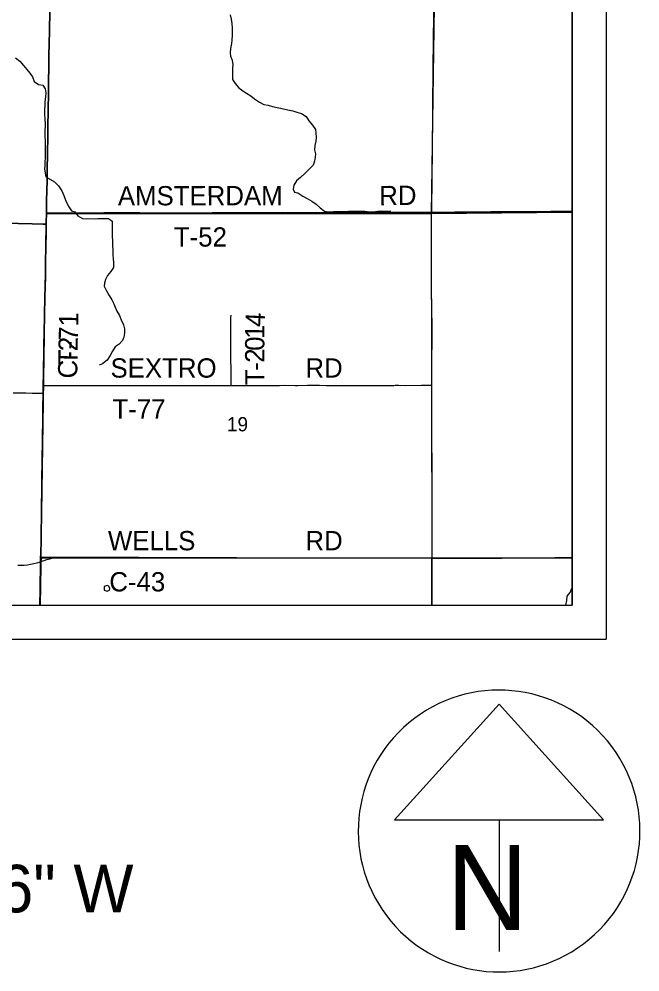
# Model space of a CAD drawing. Extents: x -11.1 to 34, y -3.9 to 22.
# Drawn here: x 7.271 to 9.099, y 13.02 to 15.825 of the extents above; entities that cross this region are included whole.
import ezdxf

# ---------------------------------------------------------------- set-up
doc = ezdxf.new("R2010")
doc.units = 0
for name, color, linetype in [('GM_X_Corporation', 7, 'Continuous'), ('GM_X_County_Road', 7, 'Continuous'), ('GM_X_County_Road_Text', 7, 'Continuous'), ('GM_X_Minor_Lake', 7, 'Continuous'), ('GM_X_Minor_River', 7, 'Continuous'), ('GM_X_Section_Text', 7, 'Continuous'), ('GM_X_Township_Road', 7, 'Continuous'), ('GM_X_Township_Road_Text', 7, 'Continuous'), ('SH_Data', 7, 'Continuous'), ('SH_Text', 7, 'Continuous')]:
    doc.layers.add(name, color=color, linetype=linetype)

msp = doc.modelspace()

# ---------------------------------------------------------------- linework, layer by layer
at = {"layer": 'GM_X_Corporation'}
for points in [[(7.3613, 15.8526), (7.3601, 15.7867), (7.3596, 15.7569), (7.3589, 15.7153), (7.3582, 15.6817), (7.3577, 15.6439), (7.3576, 15.6308), (7.3573, 15.6078), (7.356, 15.5071), (7.3554, 15.4686), (7.3548, 15.4413), (7.3545, 15.4251), (7.3538, 15.3866), (7.3533, 15.3537), (7.3525, 15.3176), (7.3519, 15.2928), (7.3513, 15.2636), (7.3512, 15.2541), (7.3508, 15.2263), (7.3508, 15.2219), (7.3507, 15.1996), (7.3497, 15.1505), (7.349, 15.1132), (7.3483, 15.0666), (7.3471, 15.0082), (7.3458, 14.9523), (7.345, 14.9013), (7.3443, 14.8653), (7.3436, 14.8274), (7.3433, 14.8131), (7.3425, 14.7765), (7.3422, 14.7516), (7.3421, 14.7474), (7.3418, 14.7293), (7.3418, 14.7242), (7.3413, 14.6802), (7.3406, 14.6373), (7.34, 14.6025), (7.3394, 14.5733), (7.3389, 14.5404), (7.3387, 14.5118), (7.3383, 14.482), (7.3381, 14.4702), (7.3376, 14.4223), (7.3373, 14.408), (7.3366, 14.3484), (7.3363, 14.3291), (7.3361, 14.3123), (7.3355, 14.2893), (7.3346, 14.2521), (7.3343, 14.2397), (7.3341, 14.2279), (7.3337, 14.1993), (7.3332, 14.1738), (7.3327, 14.1458), (7.332, 14.1), (8.9, 14.1), (8.9, 19.2515)], [(7.3613, 15.8526), (7.3601, 15.7867), (7.3596, 15.7569), (7.3589, 15.7153), (7.3582, 15.6817), (7.3577, 15.6439), (7.3576, 15.6308), (7.3573, 15.6078), (7.356, 15.5071), (7.3554, 15.4686), (7.3548, 15.4413), (7.3545, 15.4251), (7.3538, 15.3866), (7.3533, 15.3537), (7.3525, 15.3176), (7.3519, 15.2928), (7.3513, 15.2636), (7.3512, 15.2541), (7.3522, 15.2541), (7.3626, 15.2543), (7.3874, 15.2543), (7.4377, 15.2541), (7.4824, 15.2544), (7.5203, 15.2546), (7.5502, 15.2545), (7.6017, 15.2545), (7.6266, 15.2545), (7.6856, 15.2543), (7.7416, 15.2543), (7.8398, 15.2545), (7.887, 15.2546), (7.9286, 15.2547), (7.979, 15.255), (8.0479, 15.2555), (8.1126, 15.2553), (8.1704, 15.2555), (8.2008, 15.2555), (8.2294, 15.2555), (8.2341, 15.2556), (8.2679, 15.2556), (8.3083, 15.2559), (8.3512, 15.2561), (8.3785, 15.2559), (8.4202, 15.2558), (8.4699, 15.2559), (8.4858, 15.256), (8.5022, 15.2559), (8.5538, 15.2566), (8.6115, 15.257), (8.66, 15.2575), (8.6849, 15.2577), (8.7085, 15.258), (8.7377, 15.2577), (8.7843, 15.2582), (8.8365, 15.2585), (8.8595, 15.2587), (8.9, 15.2587), (8.9, 19.2515)], [(2.1, 14.1), (7.332, 14.1), (7.3327, 14.1458), (7.3332, 14.1738), (7.3337, 14.1993), (7.3341, 14.2279), (7.3343, 14.2397), (7.3346, 14.2521), (7.3355, 14.2893), (7.3361, 14.3123), (7.3363, 14.3291), (7.3366, 14.3484), (7.3373, 14.408), (7.3376, 14.4223), (7.3381, 14.4702), (7.3383, 14.482), (7.3387, 14.5118), (7.3389, 14.5404), (7.3394, 14.5733), (7.34, 14.6025), (7.3406, 14.6373), (7.3413, 14.6802), (7.3418, 14.7242), (7.3418, 14.7293), (7.3421, 14.7474), (7.3422, 14.7516), (7.3425, 14.7765), (7.3433, 14.8131), (7.3436, 14.8274), (7.3443, 14.8653), (7.345, 14.9013), (7.3458, 14.9523), (7.3471, 15.0082), (7.3483, 15.0666), (7.349, 15.1132), (7.3497, 15.1505), (7.3507, 15.1996), (7.3508, 15.2219), (7.3508, 15.2263), (7.3512, 15.2541), (7.3513, 15.2636), (7.3519, 15.2928), (7.3525, 15.3176), (7.3533, 15.3537), (7.3538, 15.3866), (7.3545, 15.4251), (7.3548, 15.4413), (7.3554, 15.4686), (7.356, 15.5071), (7.3573, 15.6078), (7.3576, 15.6308), (7.3577, 15.6439), (7.3582, 15.6817), (7.3589, 15.7153), (7.3596, 15.7569), (7.3601, 15.7867), (7.3613, 15.8526)], [(6.3599, 15.2448), (7.3508, 15.2219), (7.3508, 15.2263), (7.3512, 15.2541), (7.3513, 15.2636), (7.3519, 15.2928), (7.3525, 15.3176), (7.3533, 15.3537), (7.3538, 15.3866), (7.3545, 15.4251), (7.3548, 15.4413), (7.3554, 15.4686), (7.356, 15.5071), (7.3573, 15.6078), (7.3576, 15.6308), (7.3577, 15.6439), (7.3582, 15.6817), (7.3589, 15.7153), (7.3596, 15.7569), (7.3601, 15.7867), (7.3613, 15.8526)], [(2.1, 14.1), (7.332, 14.1), (7.3327, 14.1458), (7.3332, 14.1738), (7.3337, 14.1993), (7.3341, 14.2279), (7.3343, 14.2397), (7.3346, 14.2521), (7.3355, 14.2893), (7.3361, 14.3123), (7.3363, 14.3291), (7.3366, 14.3484), (7.3373, 14.408), (7.3376, 14.4223), (7.3381, 14.4702), (7.3383, 14.482), (7.3387, 14.5118), (7.3389, 14.5404), (7.3394, 14.5733), (7.34, 14.6025), (7.3406, 14.6373), (7.3413, 14.6802), (7.3418, 14.7242), (7.3418, 14.7293), (7.3421, 14.7474), (7.3422, 14.7516), (7.3425, 14.7765), (7.3433, 14.8131), (7.3436, 14.8274), (7.3443, 14.8653), (7.345, 14.9013), (7.3458, 14.9523), (7.3471, 15.0082), (7.3483, 15.0666), (7.349, 15.1132), (7.3497, 15.1505), (7.3507, 15.1996), (7.3508, 15.2219), (6.3599, 15.2448)]]:
    msp.add_lwpolyline(points, dxfattribs=at)
for points in [[(8.9, 15.2568), (8.9, 16.2758), (8.4993, 16.2731), (8.4849, 15.2528)], [(7.332, 14.1), (8.9, 14.1), (8.9, 15.2587), (8.8595, 15.2587), (8.8365, 15.2585), (8.7843, 15.2582), (8.7377, 15.2577), (8.7085, 15.258), (8.6849, 15.2577), (8.66, 15.2575), (8.6115, 15.257), (8.5538, 15.2566), (8.5022, 15.2559), (8.4858, 15.256), (8.4699, 15.2559), (8.4202, 15.2558), (8.3785, 15.2559), (8.3512, 15.2561), (8.3083, 15.2559), (8.2679, 15.2556), (8.2341, 15.2556), (8.2294, 15.2555), (8.2008, 15.2555), (8.1704, 15.2555), (8.1126, 15.2553), (8.0479, 15.2555), (7.979, 15.255), (7.9286, 15.2547), (7.887, 15.2546), (7.8398, 15.2545), (7.7416, 15.2543), (7.6856, 15.2543), (7.6266, 15.2545), (7.6017, 15.2545), (7.5502, 15.2545), (7.5203, 15.2546), (7.4824, 15.2544), (7.4377, 15.2541), (7.3874, 15.2543), (7.3626, 15.2543), (7.3522, 15.2541), (7.3512, 15.2541), (7.3508, 15.2263), (7.3508, 15.2219), (7.3507, 15.1996), (7.3497, 15.1505), (7.349, 15.1132), (7.3483, 15.0666), (7.3471, 15.0082), (7.3458, 14.9523), (7.345, 14.9013), (7.3443, 14.8653), (7.3436, 14.8274), (7.3433, 14.8131), (7.3425, 14.7765), (7.3422, 14.7516), (7.3421, 14.7474), (7.3418, 14.7293), (7.3418, 14.7242), (7.3413, 14.6802), (7.3406, 14.6373), (7.34, 14.6025), (7.3394, 14.5733), (7.3389, 14.5404), (7.3387, 14.5118), (7.3383, 14.482), (7.3381, 14.4702), (7.3376, 14.4223), (7.3373, 14.408), (7.3366, 14.3484), (7.3363, 14.3291), (7.3361, 14.3123), (7.3355, 14.2893), (7.3346, 14.2521), (7.3343, 14.2397), (7.3341, 14.2279), (7.3337, 14.1993), (7.3332, 14.1738), (7.3327, 14.1458)], [(8.4849, 15.2528), (8.4868, 14.2379), (7.3356, 14.241), (7.3508, 15.2218), (7.3513, 15.2526)], [(8.9, 14.2394), (8.9, 15.2568), (8.4849, 15.2528), (8.4868, 14.2379)], [(7.3334, 14.1), (8.486, 14.1), (8.4868, 14.2379), (7.3356, 14.241), (7.3352, 14.2157)], [(8.486, 14.1), (8.9, 14.1), (8.9, 14.2394), (8.4868, 14.2379)]]:
    msp.add_lwpolyline(points, close=True, dxfattribs=at)
at = {"layer": 'GM_X_County_Road'}
for p, q in [((7.342, 14.7237), (7.3423, 14.7469)), ((7.3343, 14.2273), (7.3346, 14.2392))]:
    msp.add_line(p, q, dxfattribs=at)
for points in [[(7.3514, 15.2535), (7.3515, 15.263), (7.3522, 15.2922), (7.3525, 15.3047), (7.3528, 15.3171), (7.3536, 15.3531), (7.3538, 15.3696), (7.3541, 15.3861), (7.3544, 15.4047), (7.3547, 15.4246), (7.3551, 15.4407), (7.3554, 15.4544), (7.3556, 15.4681), (7.3559, 15.4867), (7.3561, 15.4967), (7.3562, 15.5066), (7.3565, 15.5252), (7.3567, 15.5439), (7.357, 15.5625), (7.3573, 15.5942), (7.3575, 15.6073), (7.3579, 15.6303), (7.3581, 15.662), (7.3584, 15.6812), (7.3591, 15.7147), (7.3594, 15.7334), (7.3596, 15.7449), (7.3603, 15.7862), (7.361, 15.8235), (7.3615, 15.8521)], [(7.351, 15.2213), (7.3512, 15.2397), (7.3514, 15.2535)], [(7.2641, 15.2244), (7.2827, 15.2238), (7.3013, 15.2232), (7.3158, 15.2228), (7.3304, 15.2224), (7.3407, 15.2219), (7.351, 15.2213)], [(7.3423, 14.7469), (7.3426, 14.7635), (7.3428, 14.7759), (7.3432, 14.7943), (7.3435, 14.8126), (7.3438, 14.8269), (7.3443, 14.8552), (7.3445, 14.8648), (7.3453, 14.9008), (7.3456, 14.9194), (7.3458, 14.9356), (7.3461, 14.9518), (7.3465, 14.9704), (7.3469, 14.989), (7.3474, 15.0077), (7.3485, 15.0661), (7.3488, 15.0847), (7.349, 15.0987), (7.3492, 15.1127), (7.3496, 15.1313), (7.3498, 15.1406), (7.3499, 15.15), (7.3503, 15.1686), (7.3506, 15.1838), (7.3509, 15.1991), (7.351, 15.2102), (7.351, 15.2213)], [(7.2536, 14.7253), (7.2723, 14.725), (7.2909, 14.7247), (7.3095, 14.7243), (7.3258, 14.724), (7.342, 14.7237)], [(7.3346, 14.2392), (7.3348, 14.2515), (7.3358, 14.2888), (7.336, 14.3003), (7.3363, 14.3118), (7.3366, 14.3286), (7.3369, 14.3478), (7.3373, 14.3851), (7.3374, 14.3963), (7.3375, 14.4075), (7.3378, 14.4218), (7.3382, 14.455), (7.3384, 14.4696), (7.3385, 14.4814), (7.3387, 14.4963), (7.3389, 14.5112), (7.3391, 14.5398), (7.3396, 14.5728), (7.3402, 14.602), (7.3408, 14.6368), (7.3411, 14.6554), (7.3415, 14.6796), (7.3417, 14.6983), (7.3419, 14.711), (7.342, 14.7237)], [(7.2669, 14.2175), (7.2764, 14.2178), (7.2859, 14.218), (7.2954, 14.219), (7.3048, 14.2205), (7.3142, 14.2224), (7.3234, 14.2248), (7.3343, 14.2273)], [(7.3323, 14.1), (7.3326, 14.1198), (7.333, 14.1453), (7.3332, 14.1593), (7.3334, 14.1733), (7.3339, 14.1987), (7.3343, 14.2273)], [(7.3343, 14.2273), (7.3343, 14.2273), (7.3445, 14.2315), (7.3528, 14.2344), (7.3615, 14.2369), (7.3645, 14.2376)], [(7.3346, 14.2392), (7.3384, 14.2392), (7.3439, 14.2392), (7.3529, 14.2394), (7.3591, 14.2392), (7.3602, 14.2391), (7.3609, 14.2391), (7.362, 14.2389), (7.3627, 14.2386), (7.3636, 14.2382), (7.3645, 14.2376)], [(7.3645, 14.2376), (7.3675, 14.2383), (7.3735, 14.2393), (7.3821, 14.2398), (7.4268, 14.2394), (7.502, 14.2392), (7.5418, 14.2393), (7.6083, 14.2391), (7.6381, 14.2391), (7.681, 14.2392), (7.7183, 14.2393), (7.7438, 14.239), (7.7823, 14.239), (7.8084, 14.2391), (7.8507, 14.239), (7.8979, 14.239), (7.9576, 14.239), (7.9911, 14.239), (8.0545, 14.2392), (8.0843, 14.2395), (8.1054, 14.2393), (8.1365, 14.2391), (8.1937, 14.2392), (8.2844, 14.239), (8.4156, 14.2391), (8.4485, 14.2391), (8.4875, 14.2394)], [(8.4875, 14.2394), (8.51, 14.2396), (8.6001, 14.2397), (8.6256, 14.2398), (8.6517, 14.2395), (8.7257, 14.2397), (8.7679, 14.2399), (8.8487, 14.2401), (8.9, 14.2402)]]:
    msp.add_lwpolyline(points, dxfattribs=at)
at = {"layer": 'GM_X_Minor_Lake'}
msp.add_line((7.5384, 14.1496), (7.5354, 14.1558), dxfattribs=at)
for points in [[(7.5354, 14.1558), (7.5301, 14.1581), (7.5213, 14.1553), (7.5215, 14.1447)], [(7.5215, 14.1447), (7.5306, 14.1418), (7.5371, 14.1443), (7.5384, 14.1496)]]:
    msp.add_lwpolyline(points, dxfattribs=at)
at = {"layer": 'GM_X_Minor_River'}
for points in [[(7.8929, 15.8382), (7.8957, 15.8252), (7.8974, 15.8122), (7.8983, 15.7989), (7.8985, 15.7882), (7.8983, 15.7779)], [(7.8983, 15.7779), (7.8973, 15.7635), (7.896, 15.7536), (7.8938, 15.7388), (7.8928, 15.7259), (7.8934, 15.716), (7.8985, 15.7041), (7.9002, 15.6919), (7.8992, 15.6808), (7.899, 15.6713), (7.8992, 15.6588), (7.8997, 15.6477), (7.9076, 15.6361), (7.9184, 15.623), (7.9297, 15.6137), (7.9402, 15.6074), (7.953, 15.5991), (7.9643, 15.5905), (7.9787, 15.5804), (7.9915, 15.5741), (8.0041, 15.5723), (8.0177, 15.5682), (8.0314, 15.5653), (8.0409, 15.5632), (8.0535, 15.56), (8.0671, 15.5567), (8.077, 15.5549), (8.0892, 15.5513), (8.1024, 15.5469), (8.116, 15.539), (8.1246, 15.5259), (8.1347, 15.5135), (8.1439, 15.5), (8.1449, 15.4905), (8.1458, 15.4768), (8.1448, 15.4661), (8.1423, 15.4532), (8.1413, 15.4407), (8.1434, 15.4289), (8.1432, 15.4193), (8.1411, 15.4072), (8.1374, 15.3951), (8.125, 15.3839), (8.113, 15.372), (8.0998, 15.3593), (8.0877, 15.3488), (8.0799, 15.3368), (8.0781, 15.325), (8.0818, 15.3154), (8.092, 15.3137), (8.1064, 15.3036), (8.1192, 15.2969), (8.1328, 15.289), (8.1456, 15.28), (8.1576, 15.2699), (8.17, 15.2594), (8.1826, 15.2576), (8.1956, 15.2585), (8.209, 15.259), (8.2185, 15.2585), (8.2284, 15.2591), (8.2414, 15.2596), (8.2521, 15.2601), (8.2658, 15.2595), (8.2765, 15.2597), (8.2891, 15.2594), (8.3032, 15.2584), (8.3143, 15.2582), (8.3269, 15.2595), (8.3391, 15.2604), (8.3525, 15.2598), (8.3654, 15.2599)], [(7.2602, 15.7113), (7.2732, 15.7015), (7.2835, 15.6886), (7.2942, 15.6773), (7.3026, 15.6661), (7.3107, 15.6556), (7.3156, 15.6415), (7.3279, 15.6332), (7.3411, 15.6305), (7.3481, 15.6197), (7.3493, 15.6083), (7.349, 15.5961), (7.3471, 15.5814), (7.3464, 15.5707), (7.3461, 15.5586), (7.3461, 15.5453), (7.3469, 15.5316), (7.3473, 15.5171), (7.3466, 15.4906), (7.3467, 15.4795), (7.3475, 15.4674), (7.3475, 15.4533), (7.3476, 15.4423), (7.3477, 15.4286), (7.3478, 15.418), (7.347, 15.4043), (7.3464, 15.3945), (7.3457, 15.3835), (7.3494, 15.3607)], [(7.3493, 15.3608), (7.3752, 15.3465), (7.3872, 15.3341), (7.3969, 15.3202), (7.4027, 15.3056), (7.4071, 15.2953), (7.4104, 15.285), (7.417, 15.2726), (7.4252, 15.2607), (7.4347, 15.2582), (7.444, 15.2466), (7.4576, 15.2384), (7.4686, 15.2378), (7.4797, 15.238), (7.4927, 15.2377), (7.5026, 15.2383), (7.5125, 15.2385), (7.5251, 15.2379), (7.5347, 15.2381), (7.5448, 15.2303), (7.545, 15.2177), (7.5448, 15.2078), (7.5453, 15.1953), (7.5451, 15.185), (7.5457, 15.1728), (7.5458, 15.1595), (7.5467, 15.1446), (7.5472, 15.1305), (7.5481, 15.121), (7.5494, 15.1077), (7.5492, 15.094), (7.5409, 15.082), (7.5315, 15.0703), (7.5252, 15.0586), (7.522, 15.0484), (7.521, 15.0389), (7.5288, 15.0255), (7.5362, 15.0116), (7.5436, 14.9993), (7.5502, 14.987), (7.5535, 14.9775), (7.5586, 14.9656), (7.5671, 14.9525), (7.5711, 14.9398), (7.5785, 14.9256), (7.5817, 14.9134), (7.5814, 14.9005), (7.5793, 14.8887), (7.5753, 14.8789), (7.566, 14.8688), (7.5536, 14.861), (7.5461, 14.8475), (7.5394, 14.835), (7.53, 14.8215), (7.5168, 14.8104), (7.5072, 14.8067)], [(8.8814, 14.1), (8.8815, 14.1004), (8.8836, 14.1137), (8.8854, 14.1262), (8.894, 14.1378), (8.9, 14.1518)]]:
    msp.add_lwpolyline(points, dxfattribs=at)
at = {"layer": 'GM_X_Township_Road'}
for p, q in [((7.342, 14.7237), (7.3423, 14.7469)), ((7.3343, 14.2273), (7.3346, 14.2392))]:
    msp.add_line(p, q, dxfattribs=at)
for points in [[(7.3514, 15.2535), (7.3515, 15.263), (7.3522, 15.2922), (7.3525, 15.3047), (7.3528, 15.3171), (7.3536, 15.3531), (7.3538, 15.3696), (7.3541, 15.3861), (7.3544, 15.4047), (7.3547, 15.4246), (7.3551, 15.4407), (7.3554, 15.4544), (7.3556, 15.4681), (7.3559, 15.4867), (7.3561, 15.4967), (7.3562, 15.5066), (7.3565, 15.5252), (7.3567, 15.5439), (7.357, 15.5625), (7.3573, 15.5942), (7.3575, 15.6073), (7.3579, 15.6303), (7.3581, 15.662), (7.3584, 15.6812), (7.3591, 15.7147), (7.3594, 15.7334), (7.3596, 15.7449), (7.3603, 15.7862), (7.361, 15.8235), (7.3615, 15.8521)], [(8.486, 15.2554), (8.4867, 15.2804), (8.4869, 15.3003), (8.4872, 15.3195), (8.4876, 15.3506), (8.4879, 15.3854), (8.488, 15.409), (8.4882, 15.4339), (8.4884, 15.4513), (8.4888, 15.4842), (8.4891, 15.509), (8.4895, 15.5718), (8.4896, 15.5892), (8.4896, 15.6066), (8.49, 15.642), (8.4904, 15.6824), (8.4906, 15.7023), (8.491, 15.7402), (8.4913, 15.7806), (8.4919, 15.8204), (8.4926, 15.8695)], [(7.351, 15.2213), (7.3512, 15.2397), (7.3514, 15.2535)], [(7.3514, 15.2535), (7.3628, 15.2538), (7.3876, 15.2538), (7.4379, 15.2535), (7.4827, 15.2539), (7.5206, 15.254), (7.5504, 15.2539), (7.602, 15.254), (7.6268, 15.2539), (7.6859, 15.2537), (7.7418, 15.2538), (7.84, 15.254), (7.8872, 15.254), (7.9288, 15.2542), (7.9792, 15.2545), (7.9812, 15.2545)], [(7.9812, 15.2545), (8.0482, 15.255), (8.1128, 15.2548), (8.1706, 15.2549), (8.201, 15.2549), (8.2296, 15.255), (8.2344, 15.255), (8.2681, 15.2551), (8.3085, 15.2553), (8.3514, 15.2555), (8.3788, 15.2553), (8.4204, 15.2553), (8.4701, 15.2553), (8.486, 15.2554)], [(8.4865, 14.7475), (8.4866, 14.7821), (8.4867, 14.8113), (8.4869, 14.8337), (8.4871, 14.8697), (8.4871, 14.8884), (8.4872, 14.9207), (8.4871, 14.9313), (8.4867, 14.9611), (8.486, 14.9945), (8.4859, 15.0095), (8.4859, 15.0362), (8.4858, 15.0647), (8.4858, 15.1107), (8.4858, 15.1244), (8.4858, 15.1387), (8.4858, 15.1673), (8.4858, 15.1878), (8.4859, 15.2114), (8.4859, 15.2501), (8.486, 15.2554)], [(8.486, 15.2554), (8.5024, 15.2554), (8.554, 15.2561), (8.6118, 15.2564), (8.6603, 15.257), (8.6851, 15.2571), (8.7087, 15.2575), (8.7379, 15.2572), (8.7845, 15.2577), (8.8367, 15.258), (8.8597, 15.2582), (8.9, 15.2581)], [(7.3423, 14.7469), (7.3426, 14.7635), (7.3428, 14.7759), (7.3432, 14.7943), (7.3435, 14.8126), (7.3438, 14.8269), (7.3443, 14.8552), (7.3445, 14.8648), (7.3453, 14.9008), (7.3456, 14.9194), (7.3458, 14.9356), (7.3461, 14.9518), (7.3465, 14.9704), (7.3469, 14.989), (7.3474, 15.0077), (7.3485, 15.0661), (7.3488, 15.0847), (7.349, 15.0987), (7.3492, 15.1127), (7.3496, 15.1313), (7.3498, 15.1406), (7.3499, 15.15), (7.3503, 15.1686), (7.3506, 15.1838), (7.3509, 15.1991), (7.351, 15.2102), (7.351, 15.2213)], [(7.8953, 14.747), (7.8954, 14.7519), (7.8954, 14.7882), (7.8953, 14.7987), (7.8948, 14.8193), (7.8947, 14.8286), (7.8947, 14.8435), (7.8947, 14.8684), (7.8947, 14.882), (7.8947, 14.8901), (7.8947, 14.8963), (7.8946, 14.9075), (7.8946, 14.9468), (7.8954, 14.9533)], [(7.3423, 14.7469), (7.349, 14.747), (7.3528, 14.747), (7.3745, 14.7469), (7.4025, 14.7469), (7.428, 14.7469), (7.4752, 14.7468), (7.5255, 14.7469), (7.5628, 14.747), (7.5696, 14.7471), (7.5802, 14.747), (7.5982, 14.7469), (7.6336, 14.7471), (7.6932, 14.747), (7.7106, 14.747), (7.7237, 14.747), (7.7554, 14.7467), (7.7846, 14.7466), (7.7951, 14.7466), (7.8368, 14.747), (7.8573, 14.7472), (7.8865, 14.7471), (7.8953, 14.747)], [(7.8953, 14.747), (7.9144, 14.7469), (7.9306, 14.747), (7.948, 14.7472), (7.9691, 14.7472), (7.989, 14.747), (7.9958, 14.7471), (8.0275, 14.7471), (8.0381, 14.7471), (8.0511, 14.7473), (8.084, 14.7472), (8.0915, 14.7472), (8.1207, 14.7473), (8.1251, 14.7473), (8.1393, 14.7473), (8.1455, 14.7474), (8.1561, 14.7473), (8.1766, 14.7472), (8.1828, 14.7472), (8.2369, 14.7471), (8.2555, 14.7472), (8.263, 14.7471), (8.2909, 14.747), (8.3133, 14.7469), (8.3245, 14.7469), (8.3525, 14.7471), (8.3748, 14.7472), (8.3785, 14.7473), (8.3879, 14.7474), (8.4096, 14.7472), (8.4562, 14.7475), (8.4718, 14.7475), (8.4817, 14.7475), (8.4865, 14.7475)], [(8.4875, 14.2394), (8.4877, 14.2584), (8.4878, 14.2783), (8.4876, 14.3012), (8.4876, 14.3211), (8.4877, 14.3342), (8.4876, 14.3596), (8.4876, 14.3839), (8.4874, 14.4187), (8.4873, 14.4479), (8.4873, 14.464), (8.4872, 14.4858), (8.4872, 14.5044), (8.4871, 14.5305), (8.4868, 14.5678), (8.4867, 14.5951), (8.4866, 14.6368), (8.4864, 14.6566), (8.4864, 14.6952), (8.4864, 14.7095), (8.4863, 14.7219), (8.4865, 14.7475)], [(7.3346, 14.2392), (7.3348, 14.2515), (7.3358, 14.2888), (7.336, 14.3003), (7.3363, 14.3118), (7.3366, 14.3286), (7.3369, 14.3478), (7.3373, 14.3851), (7.3374, 14.3963), (7.3375, 14.4075), (7.3378, 14.4218), (7.3382, 14.455), (7.3384, 14.4696), (7.3385, 14.4814), (7.3387, 14.4963), (7.3389, 14.5112), (7.3391, 14.5398), (7.3396, 14.5728), (7.3402, 14.602), (7.3408, 14.6368), (7.3411, 14.6554), (7.3415, 14.6796), (7.3417, 14.6983), (7.3419, 14.711), (7.342, 14.7237)], [(7.3323, 14.1), (7.3326, 14.1198), (7.333, 14.1453), (7.3332, 14.1593), (7.3334, 14.1733), (7.3339, 14.1987), (7.3343, 14.2273)], [(8.486, 14.1), (8.486, 14.1004), (8.4864, 14.1215), (8.4866, 14.1339), (8.4868, 14.1482), (8.487, 14.1637), (8.487, 14.1873), (8.4873, 14.2203), (8.4875, 14.237), (8.4875, 14.2394)]]:
    msp.add_lwpolyline(points, dxfattribs=at)
at = {"layer": 'SH_Data'}
for p, q in [((9, 21), (9, 14)), ((8.9, 20.9), (8.9, 14.1)), ((2.1, 14.1), (8.9, 14.1)), ((2, 14), (9, 14)), ((8.6845, 13.809), (8.3769, 13.4678)), ((8.9921, 13.4678), (8.6845, 13.809)), ((8.3769, 13.4678), (8.9921, 13.4678)), ((8.6845, 13.4678), (8.6845, 13.081)), ((8.6845, 13.4353), (8.6845, 13.4353)), ((8.6845, 13.4353), (8.6845, 13.4353))]:
    msp.add_line(p, q, dxfattribs=at)
msp.add_arc((8.6845, 13.4353), 0.4148, 129.7798, 129.7633, dxfattribs=at)

# ---------------------------------------------------------------- texts
at = {"layer": 'GM_X_County_Road_Text'}
for s, rotation, p in [('C-2', 89.0809, (7.4421, 14.767)), ('WELLS', 0, (7.5326, 14.2616)), ('RD', 0, (8.1142, 14.2616)), ('C-43', 0, (7.5367, 14.1405))]:
    msp.add_text(s, height=0.05682, rotation=rotation, dxfattribs=at).set_placement(p)
at = {"layer": 'GM_X_Section_Text'}
msp.add_text('19', height=0.04186, rotation=0, dxfattribs=at).set_placement((7.883, 14.6118))
at = {"layer": 'GM_X_Township_Road_Text'}
for s, height, rotation, p in [('AMSTERDAM', 0.05682, 0.1049, (7.5618, 15.2766)), ('RD', 0.05682, 0.4864, (8.3318, 15.2774)), ('T-52', 0.05682, 0, (7.7267, 15.1556)), ('T-71', 0.05682, 88.9465, (7.443, 14.8058)), ('4', 0.0568, 87.3242, (7.9934, 14.918)), ('1', 0.0568, 89.6878, (7.9932, 14.8837)), ('0', 0.0568, 90.0989, (7.9933, 14.8488)), ('2', 0.0568, 90.2186, (7.9934, 14.8138)), ('SEXTRO', 0.05682, 0, (7.5401, 14.7699)), ('-', 0.0568, 90.2449, (7.9935, 14.7905)), ('RD', 0.05682, 0, (8.1142, 14.7699)), ('T', 0.0568, 90.2357, (7.9937, 14.748)), ('T-77', 0.05682, 0, (7.5459, 14.6491))]:
    msp.add_text(s, height=height, rotation=rotation, dxfattribs=at).set_placement(p)
at = {"layer": 'SH_Data'}
msp.add_text('N', height=0.25, dxfattribs=at).set_placement((8.5292, 13.1439))
at = {"layer": 'SH_Text'}
msp.add_text('LATITUDE:  40°26\'13"  N   LONGITUDE:  84°22\'26" W', height=0.14, dxfattribs=at).set_placement((3.071, 13.1958))

doc.saveas('drawing.dxf')
